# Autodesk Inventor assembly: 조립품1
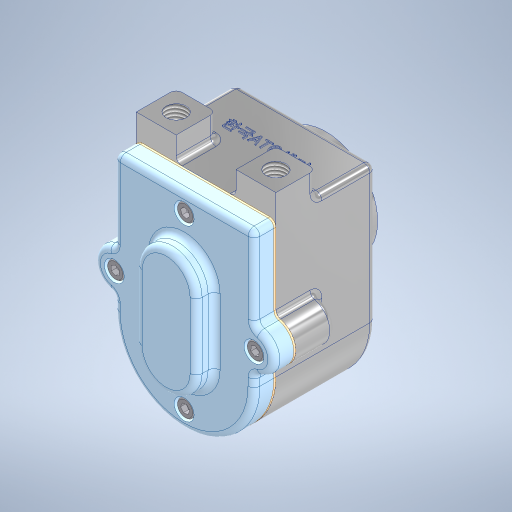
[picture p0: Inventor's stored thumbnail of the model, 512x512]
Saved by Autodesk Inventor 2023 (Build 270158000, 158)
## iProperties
Created: 2024-03
Part Number: 조립품1
Document SubType Name: Assembly
Designer: asung
Author: asung
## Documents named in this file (9)
- C:\Users\asung\Desktop\740304V1007\조립품1.iam
- C:\Users\asung\Desktop\740304V1007\본체.ipt
- C:\Users\asung\Desktop\740304V1007\오일레스 부시.ipt
- C:\Users\asung\Desktop\740304V1007\오일 실 14 25 7.ipt
- C:\Users\asung\Desktop\740304V1007\구동기어.ipt
- C:\Users\asung\Desktop\740304V1007\스퍼기어.ipt
- C:\Users\asung\Desktop\740304V1007\가스켓.ipt
- C:\Users\asung\Desktop\740304V1007\커버.ipt
- C:\Users\asung\Desktop\740304V1007\육각 소켓 머리 볼트 M5x12.ipt
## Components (2 placed, 2 different names)
1. 구동기어:1
2. 가스켓:1
